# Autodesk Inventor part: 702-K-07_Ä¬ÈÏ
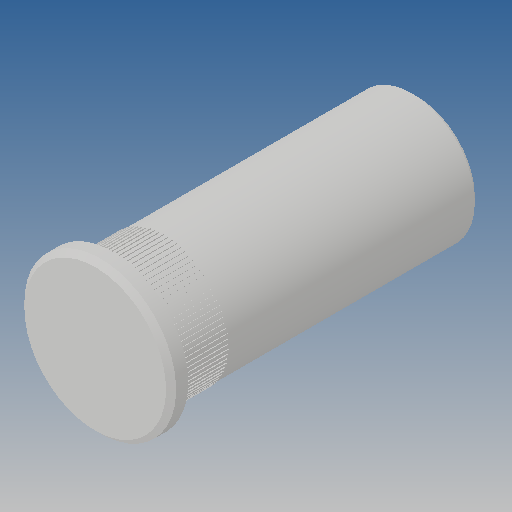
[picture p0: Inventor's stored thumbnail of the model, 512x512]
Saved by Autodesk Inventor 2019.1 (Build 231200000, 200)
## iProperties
Created: 2010-06
Part Number: 702-K-07_Ä¬ÈÏ
Material: Ogólny
Document SubType Name: Modeling
Designer: CADENGINEERING4
Density: 1 g/cm^3
Appearance: Domyślna
Author: CADENGINEERING4
Revision Number: ÈÎºÎ
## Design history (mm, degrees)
feature "NONE"
node "Bryła1"
